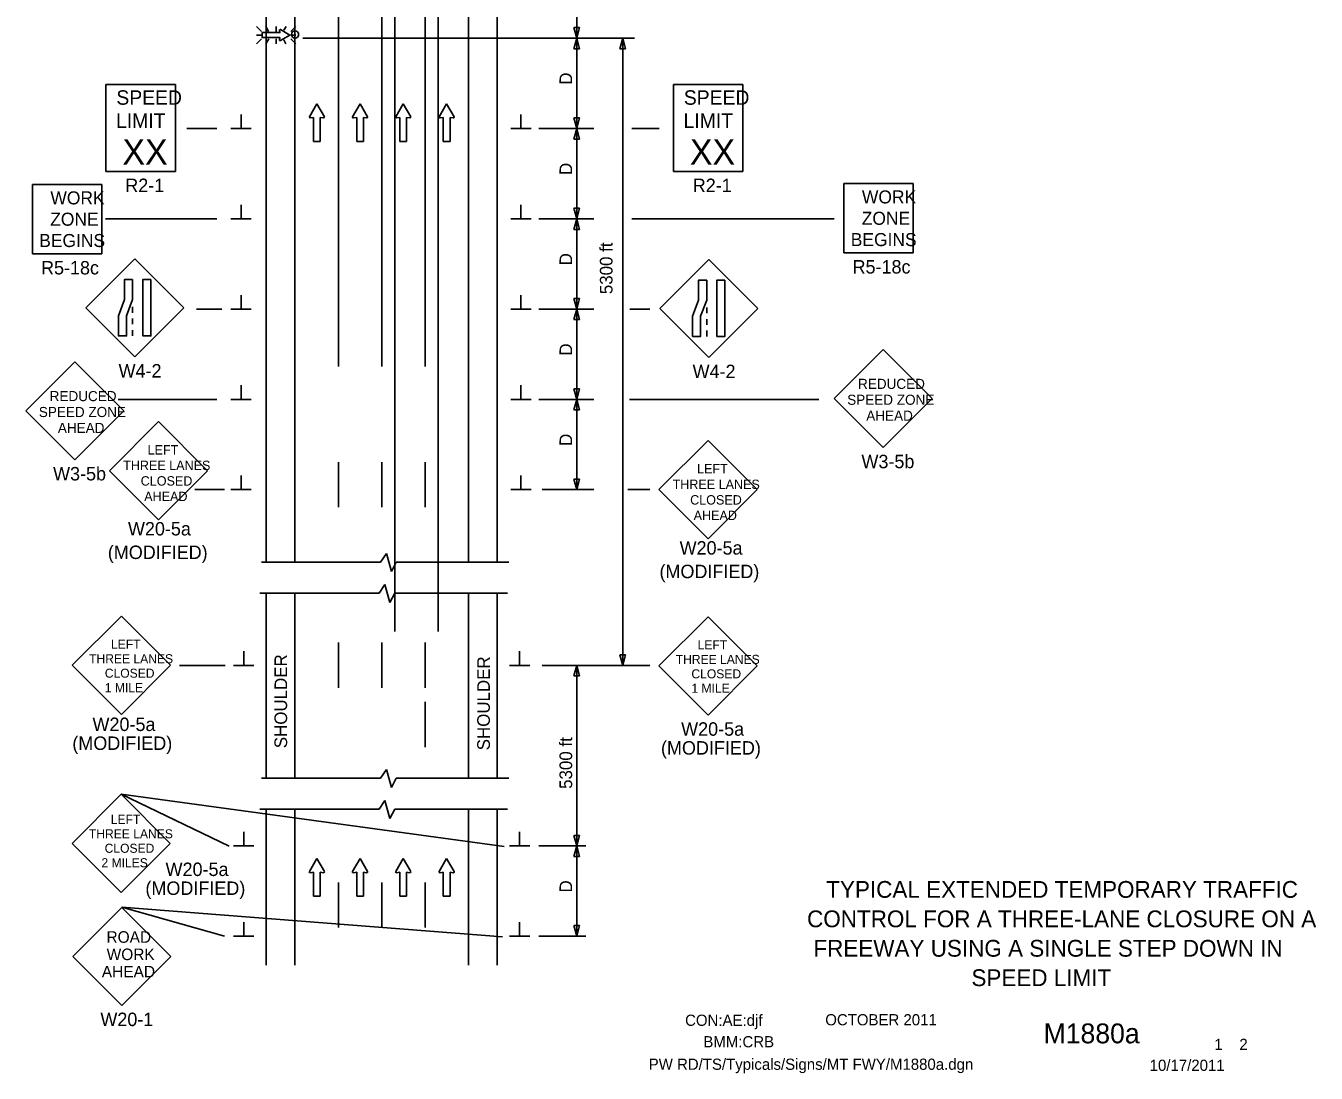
# Model space of a CAD drawing. Extents: x 16726 to 18479, y 5932 to 7023.
# Drawn here: x 16726 to 17440, y 5932 to 6512 of the extents above; entities that cross this region are included whole.
import ezdxf

# ---------------------------------------------------------------- set-up
doc = ezdxf.new("R2010")
doc.units = 0
for name, color, linetype in [('ALI_LEGAL_EX', 7, 'Continuous'), ('BORDER', 7, 'Continuous'), ('BORDER_SIGNAL_WO', 7, 'Continuous'), ('MT_SCRATCH_LEVEL_E', 7, 'Continuous'), ('PAVT_EDGE_EX', 7, 'Continuous'), ('TRAFFIC_SIGNS_PR', 7, 'Continuous'), ('TYPICAL_TEXT_DIMEN_PR', 7, 'Continuous')]:
    doc.layers.add(name, color=color, linetype=linetype)

msp = doc.modelspace()

# ---------------------------------------------------------------- linework, layer by layer
at = {"layer": 'ALI_LEGAL_EX'}
for p, q in [((16898.69, 7022.86), (16898.69, 6323.13)), ((16922.69, 7022.86), (16922.69, 6323.13)), ((16946.69, 7022.86), (16946.69, 6323.13)), ((16929.88, 7005.57), (16929.88, 6176.39)), ((16953.88, 7005.57), (16953.88, 6176.39)), ((16953.88, 7005.57), (16953.88, 6176.39))]:
    msp.add_line(p, q, dxfattribs=at)
for points in [[(16898.69, 6470.26), (16898.69, 6445.26)], [(16922.69, 6470.26), (16922.69, 6445.26)], [(16946.69, 6470.26), (16946.69, 6445.26)], [(16898.69, 6370.26), (16898.69, 6345.26)], [(16922.69, 6370.26), (16922.69, 6345.26)], [(16946.69, 6370.26), (16946.69, 6345.26)], [(16898.69, 6270.26), (16898.69, 6245.26)], [(16922.69, 6270.26), (16922.69, 6245.26)], [(16946.69, 6270.26), (16946.69, 6245.26)], [(16898.69, 6170.26), (16898.69, 6145.26)], [(16922.69, 6170.26), (16922.69, 6145.26)], [(16946.69, 6170.26), (16946.69, 6145.26)], [(16946.69, 6112.44), (16946.69, 6137.44)], [(16898.69, 6037.44), (16898.69, 6012.44)], [(16922.69, 6037.44), (16922.69, 6012.44)], [(16946.69, 6037.44), (16946.69, 6012.44)]]:
    msp.add_lwpolyline(points, dxfattribs=at)
at = {"layer": 'MT_SCRATCH_LEVEL_E'}
for p, q in [((16886.79, 6468.72), (16882.68, 6461.48)), ((16890.94, 6461.48), (16886.79, 6468.72)), ((16910.69, 6468.72), (16906.58, 6461.48)), ((16914.84, 6461.48), (16910.69, 6468.72)), ((16934.6, 6468.72), (16930.49, 6461.48)), ((16938.74, 6461.48), (16934.6, 6468.72)), ((16958.65, 6468.72), (16954.54, 6461.48)), ((16962.8, 6461.48), (16958.65, 6468.72)), ((16883.16, 6460.79), (16884.94, 6461.11)), ((16884.94, 6461.11), (16884.94, 6447.85)), ((16888.68, 6447.85), (16888.68, 6461.11)), ((16888.68, 6461.11), (16890.46, 6460.79)), ((16907.06, 6460.79), (16908.84, 6461.11)), ((16908.84, 6461.11), (16908.84, 6447.85)), ((16912.58, 6447.85), (16912.58, 6461.11)), ((16912.58, 6461.11), (16914.36, 6460.79)), ((16930.97, 6460.79), (16932.74, 6461.11)), ((16932.74, 6461.11), (16932.74, 6447.85)), ((16936.49, 6447.85), (16936.49, 6461.11)), ((16936.49, 6461.11), (16938.26, 6460.79)), ((16955.02, 6460.79), (16956.8, 6461.11)), ((16956.8, 6461.11), (16956.8, 6447.85)), ((16960.54, 6447.85), (16960.54, 6461.11)), ((16960.54, 6461.11), (16962.32, 6460.79)), ((16884.94, 6447.85), (16888.68, 6447.85)), ((16908.84, 6447.85), (16912.58, 6447.85)), ((16932.74, 6447.85), (16936.49, 6447.85)), ((16956.8, 6447.85), (16960.54, 6447.85)), ((16886.79, 6050.8), (16882.68, 6043.56)), ((16890.94, 6043.56), (16886.79, 6050.8)), ((16910.69, 6050.8), (16906.58, 6043.56)), ((16914.84, 6043.56), (16910.69, 6050.8)), ((16934.6, 6050.8), (16930.49, 6043.56)), ((16938.74, 6043.56), (16934.6, 6050.8)), ((16958.65, 6050.8), (16954.54, 6043.56)), ((16962.8, 6043.56), (16958.65, 6050.8)), ((16883.16, 6042.87), (16884.94, 6043.19)), ((16884.94, 6043.19), (16884.94, 6029.93)), ((16888.68, 6029.93), (16888.68, 6043.19)), ((16888.68, 6043.19), (16890.46, 6042.87)), ((16907.06, 6042.87), (16908.84, 6043.19)), ((16908.84, 6043.19), (16908.84, 6029.93)), ((16912.58, 6029.93), (16912.58, 6043.19)), ((16912.58, 6043.19), (16914.36, 6042.87)), ((16930.97, 6042.87), (16932.74, 6043.19)), ((16932.74, 6043.19), (16932.74, 6029.93)), ((16936.49, 6029.93), (16936.49, 6043.19)), ((16936.49, 6043.19), (16938.26, 6042.87)), ((16955.02, 6042.87), (16956.8, 6043.19)), ((16956.8, 6043.19), (16956.8, 6029.93)), ((16960.54, 6029.93), (16960.54, 6043.19)), ((16960.54, 6043.19), (16962.32, 6042.87)), ((16884.94, 6029.93), (16888.68, 6029.93)), ((16908.84, 6029.93), (16912.58, 6029.93)), ((16932.74, 6029.93), (16936.49, 6029.93)), ((16956.8, 6029.93), (16960.54, 6029.93))]:
    msp.add_line(p, q, dxfattribs=at)
for centre, start, end in [((16883.09, 6461.25), 150.42484, 279.96381), ((16890.53, 6461.25), 260.03619, 29.77312), ((16906.99, 6461.25), 150.42484, 279.96381), ((16914.43, 6461.25), 260.03619, 29.77312), ((16930.89, 6461.25), 150.42484, 279.96381), ((16938.33, 6461.25), 260.03619, 29.77312), ((16954.95, 6461.25), 150.42484, 279.96381), ((16962.39, 6461.25), 260.03619, 29.77312), ((16883.09, 6043.33), 150.42484, 279.96381), ((16890.53, 6043.33), 260.03619, 29.77312), ((16906.99, 6043.33), 150.42484, 279.96381), ((16914.43, 6043.33), 260.03619, 29.77312), ((16930.89, 6043.33), 150.42484, 279.96381), ((16938.33, 6043.33), 260.03619, 29.77312), ((16954.95, 6043.33), 150.42484, 279.96381), ((16962.39, 6043.33), 260.03619, 29.77312)]:
    msp.add_arc(centre, 0.463, start, end, dxfattribs=at)
at = {"layer": 'PAVT_EDGE_EX'}
for p, q in [((16858.69, 6927.61), (16858.69, 6215.05)), ((16874.69, 6927.61), (16874.69, 6215.05)), ((16970.69, 6927.61), (16970.69, 6215.05)), ((16986.69, 6927.61), (16986.69, 6215.05)), ((16858.69, 6197.69), (16858.69, 6095.26)), ((16874.69, 6197.69), (16874.69, 6095.26)), ((16970.69, 6197.69), (16970.69, 6095.25)), ((16986.69, 6197.69), (16986.69, 6095.25)), ((16858.69, 6078.1), (16858.69, 5991.64)), ((16874.69, 6078.1), (16874.69, 5991.64)), ((16970.69, 6078.11), (16970.69, 5991.64)), ((16986.69, 6078.11), (16986.69, 5991.64))]:
    msp.add_line(p, q, dxfattribs=at)
at = {"layer": 'TRAFFIC_SIGNS_PR'}
for p, q in [((16856.17, 6508.7), (16853.35, 6511.52)), ((16858.47, 6511.52), (16860.1, 6508.7)), ((16864.26, 6508.7), (16864.26, 6511.52)), ((16869.73, 6511.52), (16868.52, 6509.43)), ((16875.16, 6511.52), (16872.34, 6508.7)), ((16856.17, 6506.67), (16853.35, 6506.67)), ((16856.17, 6504.64), (16853.35, 6501.81)), ((16860.12, 6504.64), (16858.49, 6501.82)), ((16864.26, 6504.64), (16864.26, 6501.82)), ((16868.44, 6504), (16869.7, 6501.82)), ((16872.34, 6506.67), (16875.16, 6506.67)), ((16875.16, 6501.82), (16872.34, 6504.64)), ((16770.02, 6479.27), (16808.47, 6479.27)), ((16770.02, 6431.21), (16770.02, 6479.27)), ((16808.47, 6431.21), (16808.47, 6479.27)), ((17084.22, 6479.27), (17122.66, 6479.27)), ((17084.22, 6431.21), (17084.22, 6479.27)), ((17122.66, 6431.21), (17122.66, 6479.27)), ((16770.02, 6431.21), (16808.47, 6431.21)), ((17084.22, 6431.21), (17122.66, 6431.21)), ((16729.26, 6385.58), (16729.26, 6423.98)), ((16729.26, 6423.98), (16767.66, 6423.98)), ((16767.66, 6385.58), (16767.66, 6423.98)), ((17178.6, 6386.1), (17178.6, 6424.5)), ((17178.6, 6424.5), (17217.01, 6424.5)), ((17217.01, 6386.1), (17217.01, 6424.5)), ((16729.26, 6385.58), (16767.66, 6385.58)), ((16786.05, 6382.8), (16758.9, 6355.65)), ((16813.2, 6355.65), (16786.05, 6382.8)), ((17103.89, 6382.49), (17076.74, 6355.33)), ((17131.05, 6355.33), (17103.89, 6382.49)), ((17178.6, 6386.1), (17217.01, 6386.1)), ((16758.9, 6355.65), (16786.05, 6328.5)), ((16784.8, 6356.14), (16784.8, 6352.94)), ((16786.05, 6328.5), (16813.2, 6355.65)), ((17076.74, 6355.33), (17103.89, 6328.18)), ((17102.65, 6355.83), (17102.65, 6352.63)), ((17103.89, 6328.18), (17131.05, 6355.33)), ((16784.8, 6349.74), (16784.8, 6346.54)), ((17102.65, 6349.43), (17102.65, 6346.23)), ((16784.8, 6343.34), (16784.8, 6340.14)), ((17102.65, 6343.03), (17102.65, 6339.83)), ((17200.39, 6332.6), (17173.23, 6305.45)), ((17227.54, 6305.45), (17200.39, 6332.6)), ((16752.79, 6325.82), (16725.64, 6298.67)), ((16779.95, 6298.67), (16752.79, 6325.82)), ((17173.23, 6305.45), (17200.39, 6278.3)), ((17200.39, 6278.3), (17227.54, 6305.45)), ((16725.64, 6298.67), (16752.79, 6271.52)), ((16752.79, 6271.52), (16779.95, 6298.67)), ((16799.14, 6292.64), (16771.99, 6265.49)), ((16826.3, 6265.49), (16799.14, 6292.64)), ((17103.37, 6282.14), (17076.21, 6254.99)), ((17130.52, 6254.99), (17103.37, 6282.14)), ((16771.99, 6265.49), (16799.14, 6238.33)), ((16799.14, 6238.33), (16826.3, 6265.49)), ((17076.21, 6254.99), (17103.37, 6227.83)), ((17103.37, 6227.83), (17130.52, 6254.99)), ((16778.56, 6184.89), (16751.37, 6157.7)), ((16805.74, 6157.7), (16778.56, 6184.89)), ((17103.37, 6184.53), (17076.18, 6157.34)), ((17130.55, 6157.34), (17103.37, 6184.53)), ((16751.37, 6157.7), (16778.56, 6130.52)), ((16778.56, 6130.52), (16805.74, 6157.7)), ((17076.18, 6157.34), (17103.37, 6130.15)), ((17103.37, 6130.15), (17130.55, 6157.34)), ((16778.46, 6086.29), (16751.27, 6059.11)), ((16805.64, 6059.11), (16778.46, 6086.29)), ((16751.27, 6059.11), (16778.46, 6031.92)), ((16778.46, 6031.92), (16805.64, 6059.11)), ((16778.76, 6023.67), (16751.61, 5996.52)), ((16805.91, 5996.52), (16778.76, 6023.67)), ((16751.61, 5996.52), (16778.76, 5969.37)), ((16778.76, 5969.37), (16805.91, 5996.52))]:
    msp.add_line(p, q, dxfattribs=at)
for points in [[(16866.08, 6509.35), (16866.31, 6508.05), (16856.59, 6508.05), (16856.59, 6505.31), (16866.31, 6505.31), (16866.08, 6504.01)], [(16866.58, 6503.65), (16871.89, 6506.67), (16866.58, 6509.71)]]:
    msp.add_lwpolyline(points, dxfattribs=at)
for points in [[(16784.8, 6371.39), (16784.8, 6360.21), (16781.46, 6351.32), (16781.46, 6340.14), (16776.96, 6340.14), (16776.96, 6351.32), (16780.31, 6360.21), (16780.31, 6371.39)], [(16794.94, 6371.39), (16794.94, 6340.14), (16790.44, 6340.14), (16790.44, 6371.39)], [(17102.65, 6371.07), (17102.65, 6359.89), (17099.3, 6351.01), (17099.3, 6339.83), (17094.81, 6339.83), (17094.81, 6351.01), (17098.15, 6359.89), (17098.15, 6371.07)], [(17112.78, 6371.07), (17112.78, 6339.83), (17108.29, 6339.83), (17108.29, 6371.07)]]:
    msp.add_lwpolyline(points, close=True, dxfattribs=at)
msp.add_circle((16874.7, 6507.03), 2, dxfattribs=at)
for centre, start, end in [((16866.42, 6509.41), 61.48329, 189.95933), ((16866.42, 6503.95), 170.73078, 298.89165)]:
    msp.add_arc(centre, 0.341, start, end, dxfattribs=at)
at = {"layer": 'TYPICAL_TEXT_DIMEN_PR'}
for p, q in [((17030.69, 6504.98), (17030.69, 6535.54)), ((17030.69, 6504.98), (17029.12, 6510.84)), ((17029.12, 6510.84), (17030.69, 6510.84)), ((17030.69, 6510.84), (17032.26, 6510.84)), ((17032.26, 6510.84), (17030.69, 6504.98)), ((16878.96, 6504.98), (17062.74, 6504.98)), ((16907.09, 6504.98), (17061.13, 6504.98)), ((17029.12, 6499.12), (17030.69, 6504.98)), ((17030.69, 6504.98), (17030.69, 6454.98)), ((17030.69, 6504.98), (17032.26, 6499.12)), ((17054.56, 6499.12), (17056.13, 6504.98)), ((17056.13, 6504.98), (17056.13, 6157.67)), ((17056.13, 6504.98), (17057.7, 6499.12)), ((17030.69, 6499.12), (17029.12, 6499.12)), ((17032.26, 6499.12), (17030.69, 6499.12)), ((17056.13, 6499.12), (17054.56, 6499.12)), ((17057.7, 6499.12), (17056.13, 6499.12)), ((16844.81, 6454.98), (16844.81, 6462.77)), ((16999.82, 6454.98), (16999.82, 6462.77)), ((17030.69, 6454.98), (17029.12, 6460.84)), ((17029.12, 6460.84), (17030.69, 6460.84)), ((17030.69, 6460.84), (17032.26, 6460.84)), ((17032.26, 6460.84), (17030.69, 6454.98)), ((16831.38, 6454.98), (16814.89, 6454.98)), ((16850.44, 6454.98), (16839.19, 6454.98)), ((17005.44, 6454.98), (16994.19, 6454.98)), ((17040.19, 6454.98), (17009.69, 6454.98)), ((17029.12, 6449.12), (17030.69, 6454.98)), ((17030.69, 6454.98), (17030.69, 6404.98)), ((17030.69, 6454.98), (17032.26, 6449.12)), ((17076.41, 6454.98), (17061.13, 6454.98)), ((17030.69, 6449.12), (17029.12, 6449.12)), ((17032.26, 6449.12), (17030.69, 6449.12)), ((16844.81, 6404.98), (16844.81, 6412.77)), ((16999.82, 6404.98), (16999.82, 6412.77)), ((17030.69, 6404.98), (17029.12, 6410.84)), ((17029.12, 6410.84), (17030.69, 6410.84)), ((17030.69, 6410.84), (17032.26, 6410.84)), ((17032.26, 6410.84), (17030.69, 6404.98)), ((16831.38, 6404.98), (16769.78, 6404.98)), ((16850.44, 6404.98), (16839.19, 6404.98)), ((17005.44, 6404.98), (16994.19, 6404.98)), ((17040.19, 6404.98), (17009.69, 6404.98)), ((17029.12, 6399.12), (17030.69, 6404.98)), ((17030.69, 6404.98), (17030.69, 6354.98)), ((17030.69, 6404.98), (17032.26, 6399.12)), ((17173.2, 6404.98), (17061.19, 6404.98)), ((17030.69, 6399.12), (17029.12, 6399.12)), ((17032.26, 6399.12), (17030.69, 6399.12)), ((16844.81, 6354.98), (16844.81, 6362.77)), ((16999.82, 6354.98), (16999.82, 6362.77)), ((17030.69, 6354.98), (17029.12, 6360.84)), ((17029.12, 6360.84), (17030.69, 6360.84)), ((17030.69, 6360.84), (17032.26, 6360.84)), ((17032.26, 6360.84), (17030.69, 6354.98)), ((16834.22, 6354.98), (16820.16, 6354.98)), ((16850.44, 6354.98), (16839.19, 6354.98)), ((17005.44, 6354.98), (16994.19, 6354.98)), ((17040.19, 6354.98), (17009.69, 6354.98)), ((17029.12, 6349.12), (17030.69, 6354.98)), ((17030.69, 6354.98), (17030.69, 6304.98)), ((17030.69, 6354.98), (17032.26, 6349.12)), ((17060.13, 6354.98), (17071.13, 6354.98)), ((17030.69, 6349.12), (17029.12, 6349.12)), ((17032.26, 6349.12), (17030.69, 6349.12)), ((16844.81, 6304.98), (16844.81, 6312.77)), ((16999.82, 6304.98), (16999.82, 6312.77)), ((17030.69, 6304.98), (17029.12, 6310.84)), ((17029.12, 6310.84), (17030.69, 6310.84)), ((17030.69, 6310.84), (17032.26, 6310.84)), ((17032.26, 6310.84), (17030.69, 6304.98)), ((16831.38, 6304.98), (16776.82, 6304.98)), ((16850.44, 6304.98), (16839.19, 6304.98)), ((17005.44, 6304.98), (16994.19, 6304.98)), ((17040.19, 6304.98), (17009.69, 6304.98)), ((17029.12, 6299.12), (17030.69, 6304.98)), ((17030.69, 6304.98), (17030.69, 6254.98)), ((17030.69, 6304.98), (17032.26, 6299.12)), ((17164.69, 6304.98), (17059.87, 6304.98)), ((17030.69, 6299.12), (17029.12, 6299.12)), ((17032.26, 6299.12), (17030.69, 6299.12)), ((16844.81, 6254.98), (16844.81, 6262.77)), ((16999.82, 6254.98), (16999.82, 6262.77)), ((17030.69, 6254.98), (17029.12, 6260.84)), ((17029.12, 6260.84), (17030.69, 6260.84)), ((17030.69, 6260.84), (17032.26, 6260.84)), ((17032.26, 6260.84), (17030.69, 6254.98)), ((16835.58, 6254.98), (16819.32, 6254.98)), ((16850.44, 6254.98), (16839.19, 6254.98)), ((17005.44, 6254.98), (16994.19, 6254.98)), ((17040.19, 6254.98), (17011.64, 6254.98)), ((17071.13, 6254.98), (17058.98, 6254.98)), ((16925.31, 6219.63), (16922.05, 6214.83)), ((16928.05, 6209.69), (16925.31, 6219.63)), ((16922.05, 6214.83), (16856.11, 6214.83)), ((16930.79, 6214.83), (16928.05, 6209.69)), ((16993.12, 6214.83), (16930.79, 6214.83)), ((16924.51, 6202.49), (16921.25, 6197.69)), ((16927.25, 6192.55), (16924.51, 6202.49)), ((16921.25, 6197.69), (16855.31, 6197.69)), ((16929.99, 6197.69), (16927.25, 6192.55)), ((16992.32, 6197.69), (16929.99, 6197.69)), ((16846.32, 6157.67), (16846.32, 6165.46)), ((16999.07, 6157.67), (16999.07, 6165.46)), ((17056.13, 6157.67), (17054.56, 6163.54)), ((17054.56, 6163.54), (17056.13, 6163.54)), ((17056.13, 6163.54), (17057.7, 6163.54)), ((17057.7, 6163.54), (17056.13, 6157.67)), ((16835.96, 6157.67), (16810.82, 6157.67)), ((16840.69, 6157.67), (16851.94, 6157.67)), ((17004.69, 6157.67), (16993.44, 6157.67)), ((17071.13, 6157.67), (17011.64, 6157.67)), ((17029.12, 6151.81), (17030.69, 6157.67)), ((17030.69, 6151.81), (17029.12, 6151.81)), ((17030.69, 6157.67), (17030.69, 6057.67)), ((17030.69, 6157.67), (17032.26, 6151.81)), ((17032.26, 6151.81), (17030.69, 6151.81)), ((16922.05, 6095.23), (16856.11, 6095.23)), ((16925.31, 6100.03), (16922.05, 6095.23)), ((16928.05, 6090.1), (16925.31, 6100.03)), ((16930.79, 6095.23), (16928.05, 6090.1)), ((16993.12, 6095.23), (16930.79, 6095.23)), ((16838.18, 6057.62), (16778.46, 6086.29)), ((16778.46, 6086.29), (16990.46, 6057.32)), ((16924.51, 6082.9), (16921.25, 6078.1)), ((16927.25, 6072.96), (16924.51, 6082.9)), ((16921.25, 6078.1), (16855.31, 6078.1)), ((16929.99, 6078.1), (16927.25, 6072.96)), ((16992.32, 6078.1), (16929.99, 6078.1)), ((16846.32, 6057.67), (16846.32, 6065.46)), ((16999.07, 6057.67), (16999.07, 6065.46)), ((17030.69, 6057.67), (17029.12, 6063.54)), ((17029.12, 6063.54), (17030.69, 6063.54)), ((17030.69, 6063.54), (17032.26, 6063.54)), ((17032.26, 6063.54), (17030.69, 6057.67)), ((16840.69, 6057.67), (16851.94, 6057.67)), ((17004.69, 6057.67), (16993.44, 6057.67)), ((17035.69, 6057.67), (17009.69, 6057.67)), ((17029.12, 6051.81), (17030.69, 6057.67)), ((17030.69, 6051.81), (17029.12, 6051.81)), ((17030.69, 6057.67), (17030.69, 6007.67)), ((17030.69, 6057.67), (17032.26, 6051.81)), ((17032.26, 6051.81), (17030.69, 6051.81)), ((16778.76, 6023.74), (16835.69, 6007.67)), ((16778.76, 6023.74), (16989.57, 6007.36)), ((16846.32, 6007.67), (16846.32, 6015.46)), ((16999.07, 6007.67), (16999.07, 6015.46)), ((17030.69, 6007.67), (17029.12, 6013.54)), ((17029.12, 6013.54), (17030.69, 6013.54)), ((17030.69, 6013.54), (17032.26, 6013.54)), ((17032.26, 6013.54), (17030.69, 6007.67)), ((16840.69, 6007.67), (16851.94, 6007.67)), ((17004.69, 6007.67), (16993.44, 6007.67)), ((17035.69, 6007.67), (17009.69, 6007.67))]:
    msp.add_line(p, q, dxfattribs=at)

# ---------------------------------------------------------------- texts
at = {"layer": 'BORDER'}
for s, p in [('TYPICAL EXTENDED TEMPORARY TRAFFIC', (17168.85, 6028.96)), ('CONTROL FOR A THREE-LANE CLOSURE ON A', (17158.22, 6012.66)), ('FREEWAY USING A SINGLE STEP DOWN IN ', (17161.72, 5996.36)), ('SPEED LIMIT', (17249.22, 5980.06))]:
    msp.add_text(s, height=9.3, dxfattribs=at).set_placement(p)
at = {"layer": 'BORDER_SIGNAL_WO'}
for s, height, p in [('CON:AE:djf  ', 6.2, (17090.69, 5958.06)), ('    OCTOBER 2011', 6.2, (17159.08, 5958.34)), ('    M1880a   ', 11, (17272.86, 5948.38)), ('BMM:CRB', 6.2, (17100.81, 5946.17)), (' 1    2 ', 6.2, (17381.45, 5944.7)), ('PW RD/TS/Typicals/Signs/MT FWY/M1880a.dgn      ', 6.2, (17070.55, 5933.71)), ('10/17/2011', 6.2, (17347.93, 5933.13))]:
    msp.add_text(s, height=height, dxfattribs=at).set_placement(p)
at = {"layer": 'TRAFFIC_SIGNS_PR'}
for s, height, p in [('SPEED', 8.01, (16775.79, 6468.12)), ('SPEED', 8.01, (17089.99, 6468.12)), ('LIMIT', 8.01, (16775.63, 6455.31)), ('LIMIT', 8.01, (17089.83, 6455.31)), ('XX', 14.048, (16779.14, 6434.98)), ('XX', 14.048, (17093.34, 6434.98)), ('R2-1', 7.449, (16780.71, 6419.76)), ('R2-1', 7.449, (17094.91, 6419.76)), ('WORK', 7.217, (16739.26, 6412.95)), ('WORK', 7.217, (17188.6, 6413.47)), ('ZONE', 7.217, (17188.49, 6401.65)), ('ZONE', 7.217, (16739.15, 6401.14)), ('BEGINS', 7.217, (16733.07, 6389.33)), ('BEGINS', 7.217, (17182.42, 6389.85)), ('R5-18c', 7.44, (16734.08, 6374.14)), ('R5-18c', 7.44, (17183.42, 6374.66)), ('W4-2', 7.44, (16777.01, 6317.06)), ('W4-2', 7.44, (17094.85, 6316.74)), ('REDUCED', 5.6, (17186.44, 6310.76)), ('REDUCED', 5.6, (16738.85, 6303.98)), ('SPEED ZONE', 5.6, (17180.44, 6301.96)), ('SPEED ZONE', 5.6, (16732.84, 6295.18)), ('AHEAD', 5.6, (17191, 6293.16)), ('AHEAD', 5.6, (16743.4, 6286.38)), ('LEFT', 5.2, (16793.09, 6274.43)), ('W3-5b', 7.44, (17188.34, 6266.86)), ('W3-5b', 7.44, (16740.75, 6260.08)), ('THREE LANES', 5.2, (16779.54, 6265.82)), ('LEFT', 5.2, (17097.31, 6263.93)), ('CLOSED', 5.2, (16789.27, 6257.23)), ('THREE LANES', 5.2, (17083.76, 6255.32)), ('AHEAD', 5.2, (16791.21, 6248.62)), ('CLOSED', 5.2, (17093.49, 6246.73)), ('AHEAD', 5.2, (17095.43, 6238.12)), ('W20-5a', 7.44, (16782.21, 6229.61)), ('(MODIFIED)', 7.44, (16771.06, 6216.57)), ('W20-5a', 7.44, (17087.66, 6219.01)), ('(MODIFIED)', 7.44, (17076.52, 6205.97)), ('LEFT', 5.006, (16772.8, 6166.86)), ('LEFT', 5.006, (17097.61, 6166.5)), ('THREE LANES', 5.0062, (16760.68, 6158.85)), ('THREE LANES', 5.0062, (17085.49, 6158.49)), ('CLOSED', 5.006, (16769.38, 6150.84)), ('CLOSED', 5.006, (17094.19, 6150.48)), ('1 MILE', 5.006, (16769.37, 6142.83)), ('1 MILE', 5.006, (17094.18, 6142.47)), ('W20-5a', 7.449, (16762.56, 6121.32)), ('W20-5a', 7.449, (17088.49, 6118.71)), ('(MODIFIED)', 7.449, (16751.4, 6110.86)), ('(MODIFIED)', 7.449, (17077.33, 6108.26)), ('LEFT', 5.006, (16772.7, 6069.91)), ('THREE LANES', 5.0062, (16760.58, 6061.9)), ('CLOSED', 5.006, (16769.28, 6053.89)), ('2 MILES', 5.006, (16767.53, 6045.88)), ('W20-5a', 7.449, (16803.02, 6041.02)), ('(MODIFIED)', 7.449, (16791.86, 6030.56)), ('ROAD', 6.4, (16770.3, 6004.06)), ('WORK', 6.4, (16770.41, 5994.46)), ('AHEAD', 6.408, (16767.71, 5984.88)), ('AHEAD', 6.4, (16767.72, 5984.86)), ('W20-1', 7.44, (16766.93, 5957.93))]:
    msp.add_text(s, height=height, dxfattribs=at).set_placement(p)
at = {"layer": 'TYPICAL_TEXT_DIMEN_PR'}
for s, p in [('D', (17028.14, 6479.2)), ('D', (17028.14, 6429.2)), ('5300 ft', (17050.5, 6363.23)), ('D', (17028.14, 6379.2)), ('D', (17028.14, 6329.2)), ('D', (17028.14, 6279.2)), ('SHOULDER', (16870.32, 6111.81)), ('SHOULDER', (16982.59, 6110.64)), ('5300 ft', (17028.14, 6089.28)), ('D', (17028.14, 6031.89))]:
    msp.add_text(s, height=7, rotation=90, dxfattribs=at).set_placement(p)

doc.saveas('drawing.dxf')
